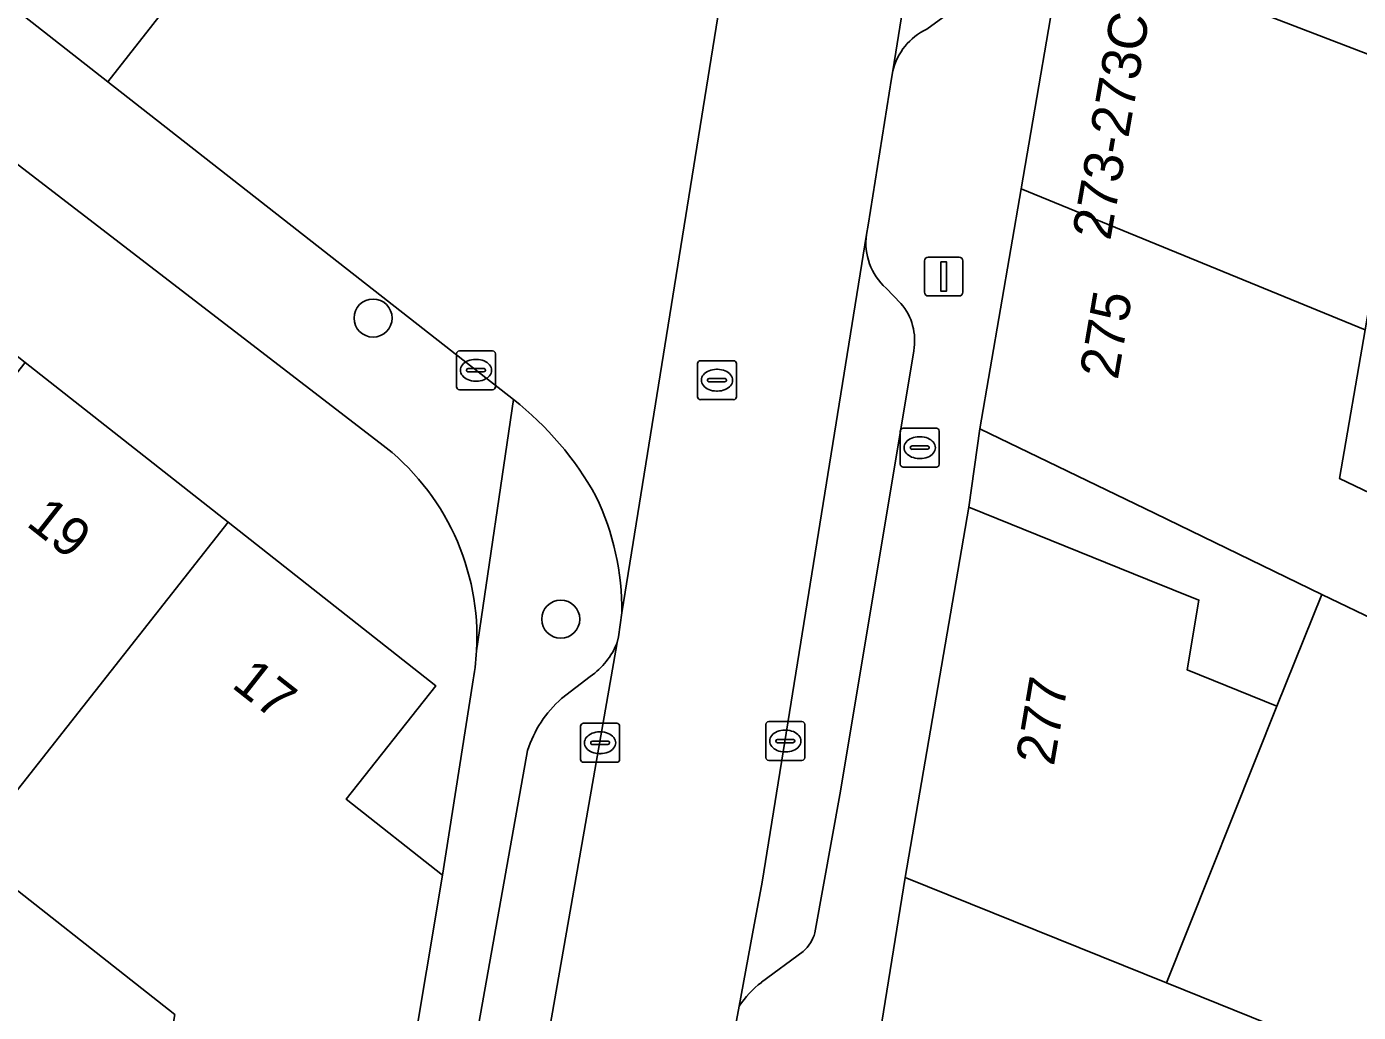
# Model space of a CAD drawing. Extents: x 159217 to 160349, y 381246 to 382172.
# Drawn here: x 160203.55 to 160237.76, y 381855.9 to 381881.22 of the extents above; entities that cross this region are included whole.
import ezdxf

# ---------------------------------------------------------------- set-up
doc = ezdxf.new("R2010")
doc.units = 0
for name, color, linetype in [('IMGEO_Boom', 7, 'Continuous'), ('IMGEO_Brandkraan', 7, 'Continuous'), ('IMGEO_Erf', 7, 'Continuous'), ('IMGEO_Kolk', 7, 'Continuous'), ('IMGEO_Lichtmast', 7, 'Continuous'), ('IMGEO_Pand', 7, 'Continuous'), ('IMGEO_Pand_nummerreeks', 7, 'Continuous'), ('IMGEO_Parkeervlak_open', 7, 'Continuous'), ('IMGEO_Rijbaan_lokaal_gesloten', 7, 'Continuous'), ('IMGEO_Rijbaan_lokaal_open', 7, 'Continuous'), ('IMGEO_Rioolput', 7, 'Continuous'), ('IMGEO_Voetpad_open', 7, 'Continuous')]:
    doc.layers.add(name, color=color, linetype=linetype)

msp = doc.modelspace()

# ---------------------------------------------------------------- linework, layer by layer
at = {"layer": 'IMGEO_Boom'}
for centre in [(160212.447, 381873.734), (160217.268, 381865.998)]:
    msp.add_circle(centre, 0.489, dxfattribs=at)
at = {"layer": 'IMGEO_Brandkraan'}
for p, q in [((160225.99, 381869.979), (160225.99, 381870.831)), ((160226.065, 381870.905), (160226.917, 381870.905)), ((160226.991, 381870.831), (160226.991, 381869.979)), ((160226.478, 381870.685), (160226.503, 381870.685)), ((160226.249, 381870.399), (160226.249, 381870.411)), ((160226.687, 381870.362), (160226.289, 381870.362)), ((160226.292, 381870.448), (160226.69, 381870.448)), ((160226.501, 381870.125), (160226.476, 381870.125)), ((160226.733, 381870.411), (160226.733, 381870.399)), ((160226.917, 381869.905), (160226.065, 381869.905))]:
    msp.add_line(p, q, dxfattribs=at)
for points in [[(160225.99, 381869.979), (160225.99, 381870.831)], [(160226.065, 381870.905), (160226.917, 381870.905)], [(160226.991, 381870.831), (160226.991, 381869.979)], [(160226.917, 381869.905), (160226.065, 381869.905)]]:
    msp.add_lwpolyline(points, dxfattribs=at)
for centre, radius, start, end in [((160226.067, 381870.829), 0.0765, 91.552, 178.448), ((160226.067, 381870.829), 0.0765, 91.552, 178.448), ((160226.915, 381870.829), 0.0765, 1.552, 88.448), ((160226.915, 381870.829), 0.0765, 1.552, 88.448), ((160226.289, 381870.408), 0.0403, 85.8775, 175.7526), ((160226.286, 381870.398), 0.0366, 178.938, 274.7102), ((160226.69, 381870.405), 0.043, 264.8664, 352.4533), ((160226.694, 381870.41), 0.0386, 1.7309, 96.639), ((160226.067, 381869.981), 0.0765, 181.552, 268.448), ((160226.067, 381869.981), 0.0765, 181.552, 268.448), ((160226.915, 381869.981), 0.0765, 271.552, 358.448), ((160226.915, 381869.981), 0.0765, 271.552, 358.448)]:
    msp.add_arc(centre, radius, start, end, dxfattribs=at)
for centre, major_axis, ratio, start_param, end_param in [((160226.477, 381870.405), (-0.387, 0.002), 0.722429, 4.712389, 7.853982), ((160226.502, 381870.405), (-0.39, 0.002), 0.717154, 1.570796, 4.712389)]:
    msp.add_ellipse(centre, major_axis=major_axis, ratio=ratio, start_param=start_param, end_param=end_param, dxfattribs=at)
at = {"layer": 'IMGEO_Erf'}
for points in [[(160212.631, 381870.524), (160193.459, 381885.263), (160149.197, 381920.443)], [(160187.741, 381885.005), (160193.073, 381880.808), (160198.289, 381876.701), (160203.505, 381872.595), (160208.721, 381868.488), (160214.055, 381864.289), (160211.757, 381861.369), (160214.232, 381859.42), (160215, 381864.331)], [(160234.878, 381881.71), (160244.187, 381878.14)], [(160237.931, 381873.428), (160237.276, 381869.612), (160244.596, 381866.11)], [(160194.265, 381844.195), (160210.591, 381839.006), (160211.378, 381842.371), (160206.447, 381843.197), (160205.272, 381843.394), (160207.355, 381855.837), (160201.892, 381860.137)]]:
    msp.add_lwpolyline(points, dxfattribs=at)
msp.add_lwpolyline([(160227.749, 381868.875), (160232.343, 381867.021), (160233.665, 381866.487), (160233.358, 381864.698), (160235.668, 381863.765), (160236.825, 381866.634), (160232.538, 381868.709), (160228.036, 381870.887)], close=True, dxfattribs=at)
for centre, radius, start, end in [((160208.853, 381865.529), 6.263, 356.8657, 52.8927), ((160208.961, 381865.513), 6.153, 348.9218, 356.96)]:
    msp.add_arc(centre, radius, start, end, dxfattribs=at)
at = {"layer": 'IMGEO_Kolk'}
for p, q in [((160214.664, 381872.893), (160215.516, 381872.893)), ((160214.589, 381871.967), (160214.589, 381872.819)), ((160215.077, 381872.673), (160215.102, 381872.673)), ((160215.59, 381872.819), (160215.59, 381871.967)), ((160214.848, 381872.387), (160214.848, 381872.399)), ((160215.286, 381872.35), (160214.888, 381872.35)), ((160214.891, 381872.436), (160215.289, 381872.436)), ((160215.332, 381872.399), (160215.332, 381872.387)), ((160215.516, 381871.893), (160214.664, 381871.893)), ((160215.1, 381872.113), (160215.075, 381872.113)), ((160217.853, 381863.322), (160218.705, 381863.322)), ((160222.536, 381862.441), (160222.536, 381863.293)), ((160222.611, 381863.367), (160223.463, 381863.367)), ((160223.537, 381863.293), (160223.537, 381862.441)), ((160217.778, 381862.396), (160217.778, 381863.248)), ((160218.266, 381863.102), (160218.291, 381863.102)), ((160218.779, 381863.248), (160218.779, 381862.396)), ((160223.024, 381863.147), (160223.049, 381863.147)), ((160218.037, 381862.816), (160218.037, 381862.828)), ((160218.475, 381862.779), (160218.077, 381862.779)), ((160218.08, 381862.865), (160218.478, 381862.865)), ((160218.521, 381862.828), (160218.521, 381862.816)), ((160222.795, 381862.861), (160222.795, 381862.873)), ((160223.233, 381862.824), (160222.835, 381862.824)), ((160222.838, 381862.91), (160223.236, 381862.91)), ((160223.279, 381862.873), (160223.279, 381862.861)), ((160218.705, 381862.322), (160217.853, 381862.322)), ((160218.289, 381862.542), (160218.264, 381862.542)), ((160223.463, 381862.367), (160222.611, 381862.367)), ((160223.047, 381862.587), (160223.022, 381862.587))]:
    msp.add_line(p, q, dxfattribs=at)
for points in [[(160214.664, 381872.893), (160215.516, 381872.893)], [(160214.589, 381871.967), (160214.589, 381872.819)], [(160215.59, 381872.819), (160215.59, 381871.967)], [(160215.516, 381871.893), (160214.664, 381871.893)], [(160217.853, 381863.322), (160218.705, 381863.322)], [(160222.536, 381862.441), (160222.536, 381863.293)], [(160222.611, 381863.367), (160223.463, 381863.367)], [(160223.537, 381863.293), (160223.537, 381862.441)], [(160217.778, 381862.396), (160217.778, 381863.248)], [(160218.779, 381863.248), (160218.779, 381862.396)], [(160218.705, 381862.322), (160217.853, 381862.322)], [(160223.463, 381862.367), (160222.611, 381862.367)]]:
    msp.add_lwpolyline(points, dxfattribs=at)
for centre, radius, start, end in [((160214.666, 381872.817), 0.0765, 91.552, 178.448), ((160214.666, 381872.817), 0.0765, 91.552, 178.448), ((160215.514, 381872.817), 0.0765, 1.552, 88.448), ((160215.514, 381872.817), 0.0765, 1.552, 88.448), ((160214.888, 381872.396), 0.0403, 85.8775, 175.7526), ((160214.885, 381872.386), 0.0366, 178.938, 274.7102), ((160215.289, 381872.393), 0.043, 264.8664, 352.4533), ((160215.293, 381872.398), 0.0386, 1.7309, 96.639), ((160214.666, 381871.969), 0.0765, 181.552, 268.448), ((160214.666, 381871.969), 0.0765, 181.552, 268.448), ((160215.514, 381871.969), 0.0765, 271.552, 358.448), ((160215.514, 381871.969), 0.0765, 271.552, 358.448), ((160217.855, 381863.246), 0.0765, 91.552, 178.448), ((160217.855, 381863.246), 0.0765, 91.552, 178.448), ((160218.703, 381863.246), 0.0765, 1.552, 88.448), ((160218.703, 381863.246), 0.0765, 1.552, 88.448), ((160222.613, 381863.291), 0.0765, 91.552, 178.448), ((160222.613, 381863.291), 0.0765, 91.552, 178.448), ((160223.461, 381863.291), 0.0765, 1.552, 88.448), ((160223.461, 381863.291), 0.0765, 1.552, 88.448), ((160218.077, 381862.825), 0.0403, 85.8775, 175.7526), ((160218.074, 381862.815), 0.0366, 178.938, 274.7102), ((160218.478, 381862.822), 0.043, 264.8664, 352.4533), ((160218.482, 381862.827), 0.0386, 1.7309, 96.639), ((160222.835, 381862.87), 0.0403, 85.8775, 175.7526), ((160222.832, 381862.86), 0.0366, 178.938, 274.7102), ((160223.236, 381862.867), 0.043, 264.8664, 352.4533), ((160223.24, 381862.872), 0.0386, 1.7309, 96.639), ((160217.855, 381862.398), 0.0765, 181.552, 268.448), ((160217.855, 381862.398), 0.0765, 181.552, 268.448), ((160218.703, 381862.398), 0.0765, 271.552, 358.448), ((160218.703, 381862.398), 0.0765, 271.552, 358.448), ((160222.613, 381862.443), 0.0765, 181.552, 268.448), ((160222.613, 381862.443), 0.0765, 181.552, 268.448), ((160223.461, 381862.443), 0.0765, 271.552, 358.448), ((160223.461, 381862.443), 0.0765, 271.552, 358.448)]:
    msp.add_arc(centre, radius, start, end, dxfattribs=at)
for centre, major_axis, ratio, start_param, end_param in [((160215.076, 381872.393), (-0.387, 0.002), 0.722429, 4.712389, 7.853982), ((160215.101, 381872.393), (-0.39, 0.002), 0.717154, 1.570796, 4.712389), ((160218.265, 381862.822), (-0.387, 0.002), 0.722429, 4.712389, 7.853982), ((160218.29, 381862.822), (-0.39, 0.002), 0.717154, 1.570796, 4.712389), ((160223.023, 381862.867), (-0.387, 0.002), 0.722429, 4.712389, 7.853982), ((160223.048, 381862.867), (-0.39, 0.002), 0.717154, 1.570796, 4.712389)]:
    msp.add_ellipse(centre, major_axis=major_axis, ratio=ratio, start_param=start_param, end_param=end_param, dxfattribs=at)
at = {"layer": 'IMGEO_Lichtmast'}
for p, q in [((160226.71, 381875.302), (160227.5, 381875.302)), ((160227.5, 381875.302), (160226.71, 381875.302)), ((160226.61, 381874.402), (160226.61, 381875.202)), ((160226.61, 381875.202), (160226.61, 381874.402)), ((160227.6, 381875.202), (160227.6, 381874.402)), ((160227.6, 381874.402), (160227.6, 381875.202)), ((160227.5, 381874.302), (160226.71, 381874.302)), ((160226.71, 381874.302), (160227.5, 381874.302))]:
    msp.add_line(p, q, dxfattribs=at)
msp.add_lwpolyline([(160227.03, 381875.177), (160227.18, 381875.177), (160227.18, 381874.427), (160227.03, 381874.427), (160227.03, 381875.177)], dxfattribs=at)
for centre, start, end in [((160226.71, 381875.202), 90, 180), ((160226.71, 381875.202), 90, 180), ((160227.5, 381875.202), 0, 90), ((160227.5, 381875.202), 360, 90), ((160226.71, 381874.402), 180, 270), ((160226.71, 381874.402), 180, 270), ((160227.5, 381874.402), 270, 0), ((160227.5, 381874.402), 270, 0)]:
    msp.add_arc(centre, 0.1, start, end, dxfattribs=at)
at = {"layer": 'IMGEO_Pand'}
for points in [[(160230.2, 381883.504), (160229.094, 381877.058), (160237.931, 381873.428), (160238.154, 381874.73), (160238.533, 381876.944), (160240.123, 381876.346), (160243.737, 381874.986), (160244.187, 381878.14), (160234.878, 381881.71)], [(160237.931, 381873.428), (160229.094, 381877.058), (160228.036, 381870.887), (160232.538, 381868.709), (160236.825, 381866.634), (160239.887, 381865.16), (160241.73, 381864.273), (160244.094, 381863.135), (160244.596, 381866.11), (160237.276, 381869.612)], [(160203.505, 381872.595), (160197.065, 381864.414), (160196.908, 381864.538), (160196.68, 381864.248), (160196.779, 381864.17), (160195.572, 381862.637), (160197.777, 381860.9), (160198.981, 381862.429), (160201.892, 381860.137), (160202.124, 381860.432), (160202.294, 381860.325), (160208.721, 381868.488)], [(160232.83, 381856.65), (160235.668, 381863.765), (160233.358, 381864.698), (160233.665, 381866.487), (160232.343, 381867.021), (160227.749, 381868.875), (160226.118, 381859.36)], [(160201.892, 381860.137), (160207.355, 381855.837), (160205.272, 381843.394), (160206.447, 381843.197), (160211.378, 381842.371), (160214.232, 381859.42), (160211.757, 381861.369), (160214.055, 381864.289), (160208.721, 381868.488), (160202.294, 381860.325), (160202.124, 381860.432)], [(160239.887, 381865.16), (160236.825, 381866.634), (160235.668, 381863.765), (160232.83, 381856.65), (160241.167, 381853.284), (160243.04, 381857.921), (160244.043, 381860.406), (160238.82, 381862.516), (160239.703, 381864.706), (160239.821, 381864.998)]]:
    msp.add_lwpolyline(points, close=True, dxfattribs=at)
at = {"layer": 'IMGEO_Parkeervlak_open'}
for points in [[(160226.932, 381887.147), (160225.799, 381880.087)], [(160226.669, 381881.158), (160227.177, 381881.526)], [(160225.124, 381875.883), (160222.445, 381859.244), (160222.198, 381857.916), (160221.852, 381856.054)], [(160226.006, 381874.112), (160225.625, 381874.506)], [(160223.798, 381857.942), (160224.451, 381861.576), (160226.336, 381872.894)], [(160214.066, 381838.814), (160218.718, 381865.398)], [(160218.027, 381864.528), (160217.291, 381863.957)], [(160216.414, 381862.624), (160214.721, 381853.115), (160212.71, 381842.096)], [(160222.422, 381856.667), (160223.497, 381857.456)]]:
    msp.add_lwpolyline(points, dxfattribs=at)
for centre, radius, start, end in [((160227.369, 381879.701), 1.617, 115.6486, 166.1757), ((160226.67, 381875.666), 1.562, 172.0134, 227.9728), ((160224.886, 381873.155), 1.474, 349.8086, 40.5105), ((160216.909, 381866.125), 1.95, 304.9858, 338.0973), ((160219.262, 381861.705), 2.993, 131.1966, 162.1204), ((160222.777, 381858.238), 1.063, 312.6348, 343.8219), ((160224.043, 381854.588), 2.636, 127.9463, 146.2171)]:
    msp.add_arc(centre, radius, start, end, dxfattribs=at)
at = {"layer": 'IMGEO_Rijbaan_lokaal_gesloten'}
msp.add_lwpolyline([(160158.477, 381928.078), (160153.073, 381921.227), (160153.218, 381921.112), (160181.742, 381898.529), (160186.323, 381894.939), (160188.766, 381893.025), (160205.633, 381879.806), (160211.317, 381887.059), (160210.848, 381887.246), (160209.912, 381887.8), (160209.032, 381888.323)], close=True, dxfattribs=at)
at = {"layer": 'IMGEO_Rijbaan_lokaal_open'}
for points in [[(160223.147, 381892.916), (160218.838, 381866.161), (160218.752, 381865.545), (160218.718, 381865.398), (160214.066, 381838.814), (160214.025, 381838.635), (160218.429, 381837.617), (160220.684, 381849.759), (160220.819, 381850.486), (160221.852, 381856.054), (160222.198, 381857.916), (160222.445, 381859.244), (160225.124, 381875.883), (160225.163, 381876.124), (160225.767, 381879.887), (160225.799, 381880.087), (160226.932, 381887.147)], [(160218.838, 381866.161), (160223.147, 381892.916)], [(160211.317, 381887.059), (160205.633, 381879.806), (160216.053, 381871.639)]]:
    msp.add_lwpolyline(points, dxfattribs=at)
msp.add_lwpolyline([(160246.457, 381845.892), (160247.696, 381848.847), (160247.386, 381848.979), (160248.055, 381850.402), (160245.157, 381851.587), (160241.167, 381853.284), (160232.83, 381856.65), (160226.118, 381859.36), (160224.358, 381848.474), (160228.423, 381847.649), (160230.447, 381846.797), (160230.872, 381846.263), (160232.441, 381846.116), (160232.801, 381845.945), (160240.493, 381842.825), (160242.328, 381842.101), (160243.215, 381841.751), (160244.08, 381841.41), (160246.745, 381840.36), (160255.623, 381836.843), (160263.753, 381833.712), (160265.51, 381839.336), (160257.601, 381841.064), (160251.891, 381843.381)], close=True, dxfattribs=at)
for centre, radius, start, end in [((160211.012, 381865.19), 8.185, 28.9722, 51.9868), ((160212.105, 381866.236), 6.733, 359.3578, 25.6877)]:
    msp.add_arc(centre, radius, start, end, dxfattribs=at)
at = {"layer": 'IMGEO_Rioolput'}
for p, q in [((160220.782, 381871.712), (160220.782, 381872.564)), ((160220.857, 381872.638), (160221.709, 381872.638)), ((160221.783, 381872.564), (160221.783, 381871.712)), ((160221.084, 381872.181), (160221.482, 381872.181)), ((160221.27, 381872.418), (160221.295, 381872.418)), ((160221.041, 381872.132), (160221.041, 381872.144)), ((160221.479, 381872.095), (160221.081, 381872.095)), ((160221.293, 381871.858), (160221.268, 381871.858)), ((160221.525, 381872.144), (160221.525, 381872.132)), ((160221.709, 381871.638), (160220.857, 381871.638))]:
    msp.add_line(p, q, dxfattribs=at)
for points in [[(160220.782, 381871.712), (160220.782, 381872.564)], [(160220.857, 381872.638), (160221.709, 381872.638)], [(160221.783, 381872.564), (160221.783, 381871.712)], [(160221.709, 381871.638), (160220.857, 381871.638)]]:
    msp.add_lwpolyline(points, dxfattribs=at)
for centre, radius, start, end in [((160220.859, 381872.562), 0.0765, 91.552, 178.448), ((160220.859, 381872.562), 0.0765, 91.552, 178.448), ((160221.707, 381872.562), 0.0765, 1.552, 88.448), ((160221.707, 381872.562), 0.0765, 1.552, 88.448), ((160221.081, 381872.141), 0.0403, 85.8775, 175.7526), ((160221.486, 381872.143), 0.0386, 1.7309, 96.639), ((160221.078, 381872.131), 0.0366, 178.938, 274.7102), ((160221.482, 381872.138), 0.043, 264.8664, 352.4533), ((160220.859, 381871.714), 0.0765, 181.552, 268.448), ((160220.859, 381871.714), 0.0765, 181.552, 268.448), ((160221.707, 381871.714), 0.0765, 271.552, 358.448), ((160221.707, 381871.714), 0.0765, 271.552, 358.448)]:
    msp.add_arc(centre, radius, start, end, dxfattribs=at)
for centre, major_axis, ratio, start_param, end_param in [((160221.269, 381872.138), (-0.387, 0.002), 0.722429, 4.712389, 7.853982), ((160221.294, 381872.138), (-0.39, 0.002), 0.717154, 1.570796, 4.712389)]:
    msp.add_ellipse(centre, major_axis=major_axis, ratio=ratio, start_param=start_param, end_param=end_param, dxfattribs=at)
at = {"layer": 'IMGEO_Voetpad_open'}
for points in [[(160146.28, 381922.78), (160149.197, 381920.443), (160193.459, 381885.263), (160212.631, 381870.524)], [(160215.106, 381865.187), (160216.053, 381871.639), (160205.633, 381879.806), (160188.766, 381893.025), (160186.323, 381894.939), (160181.742, 381898.529), (160153.218, 381921.112)], [(160223.3, 381842.294), (160224.358, 381848.474), (160226.118, 381859.36), (160227.749, 381868.875), (160228.036, 381870.887), (160229.094, 381877.058), (160230.2, 381883.504), (160230.711, 381887.467), (160227.067, 381887.987), (160226.932, 381887.147)], [(160227.177, 381881.526), (160226.669, 381881.158)], [(160225.799, 381880.087), (160225.767, 381879.887), (160225.163, 381876.124), (160225.124, 381875.883)], [(160225.625, 381874.506), (160226.006, 381874.112)], [(160226.336, 381872.894), (160224.451, 381861.576), (160223.798, 381857.942)], [(160216.053, 381871.639), (160215.106, 381865.187)], [(160218.718, 381865.398), (160218.752, 381865.545), (160218.838, 381866.161)], [(160215, 381864.331), (160214.232, 381859.42), (160211.378, 381842.371), (160210.591, 381839.006), (160209.532, 381834.478), (160208.171, 381829.218), (160206.81, 381823.955), (160206.205, 381821.854), (160205.011, 381817.916), (160204.673, 381816.802), (160203.142, 381811.752), (160202.434, 381809.668), (160200.423, 381803.959), (160198.284, 381797.887), (160198.093, 381797.954), (160197.539, 381796.357), (160181.825, 381765.351), (160183.703, 381764.359), (160182.906, 381762.655), (160179.656, 381757.694), (160174.18, 381750)], [(160217.291, 381863.957), (160218.027, 381864.528)], [(160212.71, 381842.096), (160214.721, 381853.115), (160216.414, 381862.624)], [(160223.497, 381857.456), (160222.422, 381856.667)], [(160221.852, 381856.054), (160220.819, 381850.486)]]:
    msp.add_lwpolyline(points, dxfattribs=at)
for centre, radius, start, end in [((160227.369, 381879.701), 1.617, 115.6486, 166.1757), ((160226.67, 381875.666), 1.562, 172.0134, 227.9728), ((160224.886, 381873.155), 1.474, 349.8086, 40.5105), ((160211.012, 381865.19), 8.185, 28.9722, 51.9868), ((160208.853, 381865.529), 6.263, 356.8657, 52.8927), ((160212.105, 381866.236), 6.733, 359.3578, 25.6877), ((160216.909, 381866.125), 1.95, 304.9858, 338.0973), ((160208.961, 381865.513), 6.153, 348.9218, 356.96), ((160219.262, 381861.705), 2.993, 131.1966, 162.1204), ((160222.777, 381858.238), 1.063, 312.6348, 343.8219), ((160224.043, 381854.588), 2.636, 127.9463, 146.2171)]:
    msp.add_arc(centre, radius, start, end, dxfattribs=at)

# ---------------------------------------------------------------- texts
at = {"layer": 'IMGEO_Pand_nummerreeks'}
for s, rotation, p in [('273-273C', 80.0651, (160231.385, 381875.705)), ('275', 80.2657, (160231.576, 381872.128)), ('19', 321.7859, (160203.506, 381868.42)), ('17', 321.7897, (160208.781, 381864.267)), ('277', 80.2733, (160229.934, 381862.205))]:
    msp.add_text(s, height=1, rotation=rotation, dxfattribs=at).set_placement(p)

doc.saveas('drawing.dxf')
